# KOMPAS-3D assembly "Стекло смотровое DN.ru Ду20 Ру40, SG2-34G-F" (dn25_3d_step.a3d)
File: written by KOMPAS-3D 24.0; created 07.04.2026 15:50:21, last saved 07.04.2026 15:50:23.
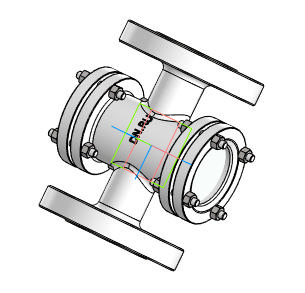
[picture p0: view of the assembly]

Document properties: Автор: Main; Полное имя файла: D:\DN.ru Аутсерс\Стекло смотровое DN.ru\Исходники\Стекло смотровое DN.ru SG2-34G-F тип В ГОСТ 21836-2021 Ду25 Ру40, углеродистая сталь, фланцевое\dn25_3d_step.a3d

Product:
- Component [detail]: Деталь  | qty 1  | pos. 1  | Масса: 4.198388; Автор: Main; additional columns: Типовые; source file: ДетальДеталь.m3d
- Component [detail]: Стекло  | qty 2  | pos. 2  | Масса: 0.08342; Автор: Main; source file: СтеклоСтекло.m3d
- Component [detail]: ANSI B18.2.4.2M - M6x1 - 10  | designation ANSI B18.2.4.2M - M6x1  | qty 16  | pos. 3  | Масса: 0.003008; Комментарий: Типы метрических   шестигранных гаек   2; Автор: Main; additional columns: Сталь, мягкая; source file: ANSI B18.2.4.2M - M6x1ANSI B18.2.4.2M - M6x1 - 10.m3d
- Part/product: Стекло смотровое DN.ru Ду20 Ру40  | designation SG2-34G-F
    Масса: 5.5
    Раздел спецификации: Прочие изделия
    Примечание: D500-00081

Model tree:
1. Массив по концентрической сетке:1  (labels: Грань.Твердое тело1; Ребро.Solid1; Грань.Solid1; Ребро.Твердое тело1)  (4 pattern instances)
     Шаг 2 = 360

Expressions: SG2-34G-F
Referenced files in D:\DN.ru Аутсерс\Стекло смотровое DN.ru\Исходники\Стекло смотровое DN.ru SG2-34G-F тип В ГОСТ 21836-2021 Ду25 Ру40, углеродистая сталь, фланцевое\: ДетальДеталь.m3d, СтеклоСтекло.m3d, ANSI B18.2.4.2M - M6x1ANSI B18.2.4.2M - M6x1 - 10.m3d
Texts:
  Стекло Стекло (1)
  Стекло Стекло (2)
  ANSI B18.2.4.2M - M6x1 ANSI B18.2.4.2M - M6x1 - 10 (1)
  ANSI B18.2.4.2M - M6x1 ANSI B18.2.4.2M - M6x1 - 10 (2)
  ANSI B18.2.4.2M - M6x1 ANSI B18.2.4.2M - M6x1 - 10 (3)
  ANSI B18.2.4.2M - M6x1 ANSI B18.2.4.2M - M6x1 - 10 (4)
  ANSI B18.2.4.2M - M6x1 ANSI B18.2.4.2M - M6x1 - 10 (5)
  ANSI B18.2.4.2M - M6x1 ANSI B18.2.4.2M - M6x1 - 10 (6)
  ANSI B18.2.4.2M - M6x1 ANSI B18.2.4.2M - M6x1 - 10 (7)
  ANSI B18.2.4.2M - M6x1 ANSI B18.2.4.2M - M6x1 - 10 (8)
  ANSI B18.2.4.2M - M6x1 ANSI B18.2.4.2M - M6x1 - 10 (9)
  ANSI B18.2.4.2M - M6x1 ANSI B18.2.4.2M - M6x1 - 10 (10)
  ANSI B18.2.4.2M - M6x1 ANSI B18.2.4.2M - M6x1 - 10 (11)
  ANSI B18.2.4.2M - M6x1 ANSI B18.2.4.2M - M6x1 - 10 (12)
  ANSI B18.2.4.2M - M6x1 ANSI B18.2.4.2M - M6x1 - 10 (13)
  ANSI B18.2.4.2M - M6x1 ANSI B18.2.4.2M - M6x1 - 10 (14)
  ANSI B18.2.4.2M - M6x1 ANSI B18.2.4.2M - M6x1 - 10 (15)
  ANSI B18.2.4.2M - M6x1 ANSI B18.2.4.2M - M6x1 - 10 (16)
  Ось Z.Начало координат
  Ось X.Начало координат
